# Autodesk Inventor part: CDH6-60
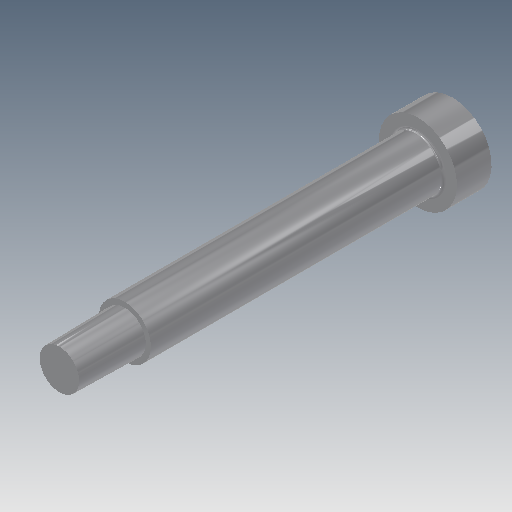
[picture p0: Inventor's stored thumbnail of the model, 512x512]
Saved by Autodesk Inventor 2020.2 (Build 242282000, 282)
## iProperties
Created: 2015-01
Part Number: CDH6-60
Material: Ogólny
Description: Straight Core Pin
Document SubType Name: Modeling
Designer: F.Stasiak
Density: 1 g/cm^3
Appearance: Domyślna
Catalog Web Link: www.expertbooks.pl
Manager: www.cadconsulting.pl
Company: Fabian Stasiak CAD Consulting
Author: F.Stasiak
Subject: Zbiór ćwiczeń. Autodesk Inventor 2020. Kurs Professional
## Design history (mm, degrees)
node "Forma_ZEGAR_260_3_ZEGAR_260_Rdzeń formujący1_Base"
feature "Solid1::Forma_ZEGAR_260_3_ZEGAR_260_Rdzeń formujący1_Base"
tag "Bryła wyprowadzona1"
node "Bryła1"
feature "Forma_ZEGAR_260_3_ZEGAR_260_Rdzeń formujący1_Base_Bodies"
